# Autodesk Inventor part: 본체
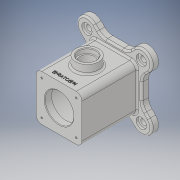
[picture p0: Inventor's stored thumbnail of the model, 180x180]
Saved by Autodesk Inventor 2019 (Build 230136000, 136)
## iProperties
Created: 2021-01
Part Number: 본체
Material: 일반
Document SubType Name: Modeling
Designer: 3DPRO15
Density: 1 g/cm^3
Appearance: 기본값
Mass: 385.865 g
Surface Area: 854.376 cm^2
Volume: 385.865 cm^3
Author: 3DPRO15
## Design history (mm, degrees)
sketch "스케치2"
  geometry: L1 (48, -48)-(-48, -48); L2 (-48, -48)-(-48, 48); L3 (-48, 48)-(48, 48); L4 (48, 48)-(48, -48); L5 (48, -48)-(-48, 48); L6 (-48, -48)-(48, 48); 1 further point
  constraints: 12 end point, 2 midpoint, 2 parallel, 1 horizontal, 1 perpendicular
  dimensions: "d9" = 96 distance of L2.end L3.end; "d10" = 96 distance of L1.end L2.end
extrude "돌출1" new body sketch "스케치2" distance "d11" = 12; taper "d12" = 0 deg
sketch "스케치3"
  geometry: L1 (-48, -48)-(48, -48) reference; L2 (48, -48)-(48, 48) reference; L3 (48, 48)-(-48, 48) reference; L4 (-48, 48)-(-48, -48) reference; L5 (-60.104, 34.648)-(-48, 22.544); L6 (-34.648, 60.104)-(-22.544, 48); L7 (-47.376, 47.376)-(0, 0); L8 (0, -93.891)-(0, 101.347) reference; A1 r 18 centre (-47.376, 47.376) between (-34.648, 60.104) and (-60.104, 34.648); 1 further point
  constraints: 8 end point, 2 coincident, 2 parallel, 2 point on circle, 2 point on line, 1 centre point
  dimensions: "d15" = 18 radius of A1; "d132" = 67 distance of L7.start L7.end; "d133" = 45 deg angle of L8 L7; "d135" = 36 distance between parallel lines of L5 L6
  node "투영된 루프1"
sketch "스케치4"
  geometry: L1 (40, 40)-(-40, 40); L2 (-40, 40)-(-40, -40); L3 (-40, -40)-(40, -40); L4 (40, -40)-(40, 40); L5 (40, 40)-(-40, -40); L6 (-40, 40)-(40, -40); 1 further point
  constraints: 12 end point, 2 midpoint, 2 parallel, 1 horizontal, 1 perpendicular
  dimensions: "d18" = 80 distance of L3.end L2.end; "d19" = 80 distance of L2.end L1.end
extrude "돌출3" join sketch "스케치4" distance "d20" = 96; taper "d21" = 0 deg
sketch "스케치5"
  geometry: C1 r 25 at (0, 0); 1 further point
  constraints: 1 centre point, 1 coincident
  dimensions: "d22" = 50 diameter of C1
extrude "돌출4" cut sketch "스케치5" distance "d23" = 12; taper "d24" = 0 deg
sketch "스케치6"
  geometry: C1 r 25 at (0, 0) reference; 2 further points
  constraints: 1 coincident
hole "구멍1" sketch "스케치6" at (0, 0) diameter "d25" = 70; stored, may be unused: countersink angle "d29" = 90 deg, drill point angle "d31" = 0 deg; dims "d26" = 6, "d27" = 4, "d28" = 2, "d30" = 84
sketch "스케치7"
  geometry: C1 r 35 at (0, 0) reference; 2 further points
  constraints: 1 coincident
hole "구멍2" sketch "스케치7" at (0, 0) diameter "d32" = 50; stored, may be unused: countersink angle "d36" = 90 deg, drill point angle "d38" = 0 deg; dims "d33" = 6, "d34" = 4, "d35" = 2, "d37" = 84
sketch "스케치8"
  geometry: 2 further points
  dimensions: "d39" = 30 horizontal distance of point (0, 0) point (-30, 30); "d40" = 30 horizontal distance of point (0, 0) point (-30, 30)
hole "구멍3" sketch "스케치8" at (-30, 30) diameter "d41" = 3.242; stored, may be unused: countersink angle "d45" = 90 deg, drill point angle "d47" = 118 deg; dims "d42" = 8, "d43" = 4, "d44" = 2, "d46" = 10
fillet "모깎기1" dims "d65" = 10
fillet "모깎기2" dims "d66" = 3
fillet "모깎기3" dims "d67" = 3
extrude "돌출6" join sketch "스케치3" distance "d83" = 12; taper "d84" = 0 deg
fillet "모깎기6" dims "d88" = 20
fillet "모깎기7" dims "d89" = 3
sketch "스케치12"
  geometry: L1 (15.74, 15)-(44.26, 15) reference; L2 (92.376, 3)-(66.77, 3) reference; C1 r 20 at (30, -44); 3 further points
  constraints: 1 centre point, 1 midpoint, 1 vertical alignment
  dimensions: "d90" = 40 diameter of C1; "d91" = 47 distance from line of L2 C1.centre
extrude "돌출7" join sketch "스케치12" distance "d92" = 15; taper "d93" = 0 deg
sketch "스케치13"
  geometry: C1 r 20 at (0, 0) reference; 2 further points
  constraints: 1 coincident
hole "구멍6" sketch "스케치13" at (0, 0) diameter "d94" = 25; stored, may be unused: countersink angle "d98" = 90 deg, drill point angle "d100" = 0 deg; dims "d95" = 8, "d96" = 30, "d97" = 8, "d99" = 10
sketch "스케치14"
  geometry: L1 (15.74, 15)-(44.26, 15) reference; L2 (60, -93)-(0, -93) reference; 3 further points
  constraints: 1 midpoint, 1 vertical alignment, 1 other
  dimensions: "d102" = 10 distance from line of L2 point (30, -83)
feature "엠보싱1" sketch "스케치14" dims "d9" = 96, "d10" = 96, "d18" = 80, "d19" = 80, "d103" = 0.5, "d104" = 0
chamfer "모따기1" distance "d105" = 1; stored, may be unused: second distance "d106" = 2, angle "d107" = 45 deg
fillet "모깎기8" dims "d118" = 3
node "작업 평면1"
sketch "스케치16"
  geometry: L1 (0, 0)-(47.376, 47.376); L2 (0, 0)-(67, 0); 1 further point
  constraints: 4 end point, 1 coincident, 1 equal length, 1 horizontal
  dimensions: "d120" = 67 distance of L1.start L1.end; "d121" = 45 deg angle of L2 L1
hole "구멍8" sketch "스케치16" at (47.376, 47.376) diameter "d122" = 10; stored, may be unused: countersink angle "d126" = 90 deg, drill point angle "d128" = 118 deg; dims "d123" = 6, "d124" = 18, "d125" = 4, "d127" = 8
node "솔리드1"
pattern_linear "직사각형 패턴1" dims "d50" = 60, "d53" = 60
pattern_circular "원형 패턴1" dims angle "d86" = 360 deg
mirror "미러3"
pattern_circular "원형 패턴3" dims angle "d130" = 360 deg
other parameters: "d0" = 134, "d13" = 36, "d119" = 54
